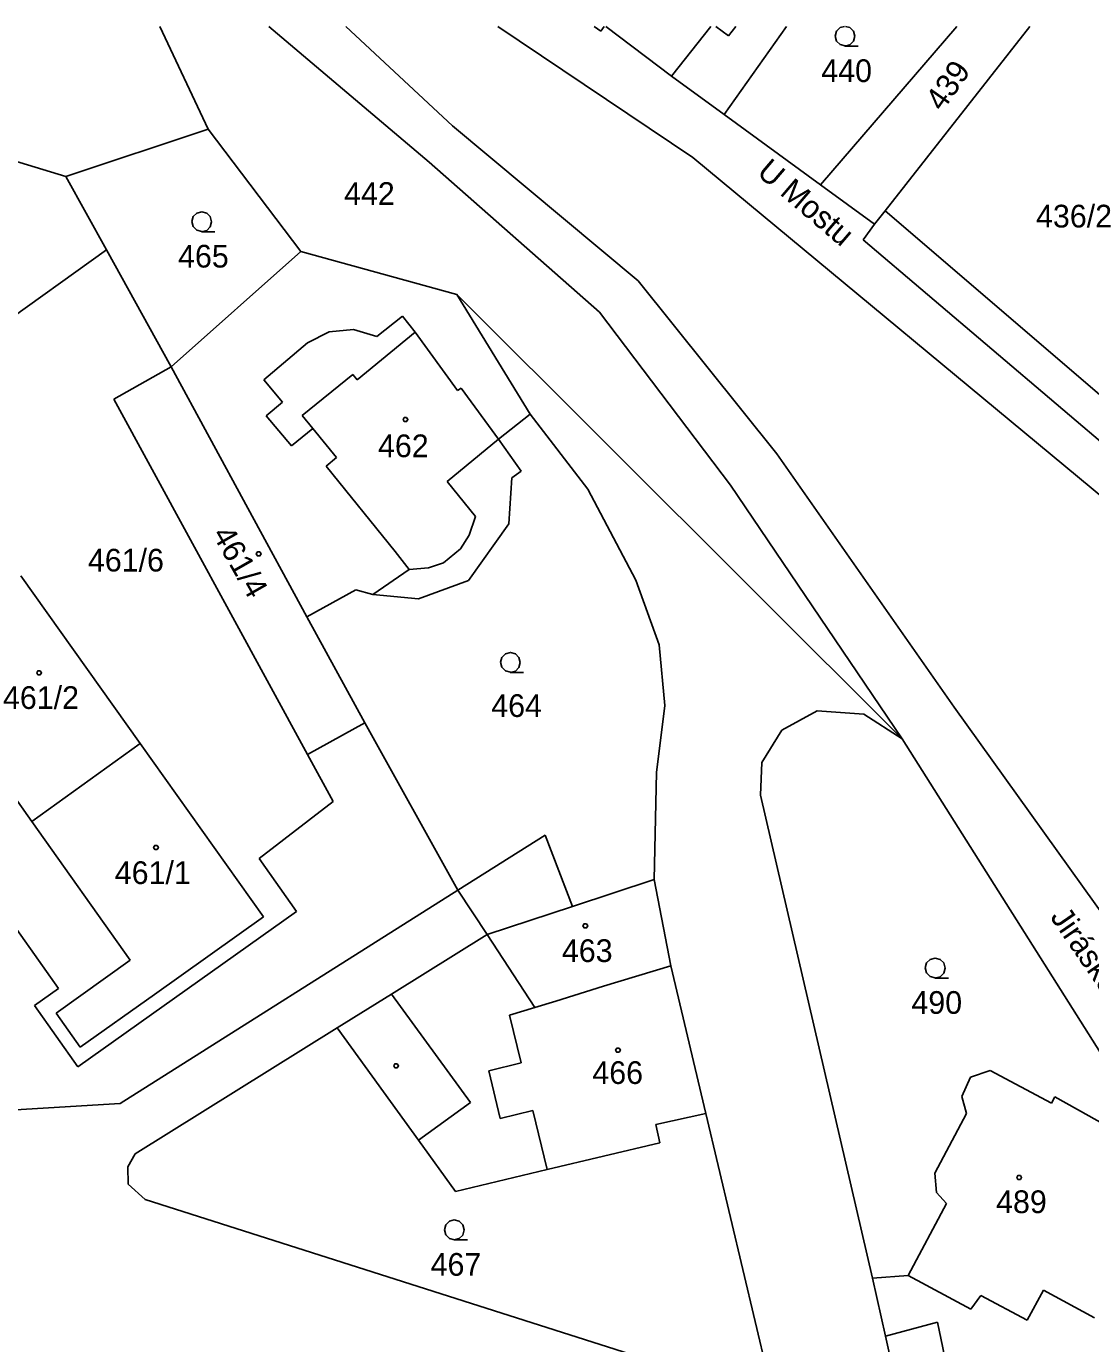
# Model space of a CAD drawing. Extents: x -621797 to -620972, y -1175539 to -1174697.
# Drawn here: x -621563.6 to -621483.9, y -1174797.6 to -1174699 of the extents above; entities that cross this region are included whole.
import ezdxf

# ---------------------------------------------------------------- set-up
doc = ezdxf.new("R2010")
doc.units = 0
for name, color, linetype in [('INZ mimo EON - nadz', 7, 'Continuous'), ('Rozvod plynu EON', 7, 'Continuous'), ('SDEL EON', 7, 'Continuous'), ('SDEL EON - popis', 7, 'Continuous'), ('Silnoproud EON', 7, 'Continuous'), ('Silnoproud EON - popis', 7, 'Continuous')]:
    doc.layers.add(name, color=color, linetype=linetype)

msp = doc.modelspace()

# ---------------------------------------------------------------- linework, layer by layer
at = {"layer": 'Rozvod plynu EON'}
for points in [[(-621535.1, -1174728.25), (-621535.01, -1174728.4), (-621535.1, -1174728.55), (-621535.28, -1174728.55), (-621535.37, -1174728.4), (-621535.28, -1174728.25)], [(-621546.09, -1174738.31), (-621546, -1174738.46), (-621546.09, -1174738.61), (-621546.27, -1174738.61), (-621546.36, -1174738.46), (-621546.27, -1174738.31)], [(-621562.53, -1174747.21), (-621562.44, -1174747.36), (-621562.53, -1174747.51), (-621562.71, -1174747.51), (-621562.8, -1174747.36), (-621562.71, -1174747.21)], [(-621553.78, -1174760.29), (-621553.69, -1174760.44), (-621553.78, -1174760.59), (-621553.96, -1174760.59), (-621554.05, -1174760.44), (-621553.96, -1174760.29)], [(-621521.63, -1174766.16), (-621521.54, -1174766.31), (-621521.63, -1174766.46), (-621521.81, -1174766.46), (-621521.9, -1174766.31), (-621521.81, -1174766.16)], [(-621519.19, -1174775.48), (-621519.1, -1174775.63), (-621519.19, -1174775.78), (-621519.37, -1174775.78), (-621519.46, -1174775.63), (-621519.37, -1174775.48)], [(-621535.8, -1174776.64), (-621535.71, -1174776.79), (-621535.8, -1174776.94), (-621535.98, -1174776.94), (-621536.07, -1174776.79), (-621535.98, -1174776.64)], [(-621489.15, -1174785), (-621489.06, -1174785.15), (-621489.15, -1174785.3), (-621489.33, -1174785.3), (-621489.42, -1174785.15), (-621489.33, -1174785)]]:
    msp.add_lwpolyline(points, close=True, dxfattribs=at)
at = {"layer": 'SDEL EON'}
for points in [[(-621502.27, -1174700.43), (-621502.65, -1174700.33), (-621502.92, -1174700.06), (-621503.02, -1174699.69), (-621502.92, -1174699.32), (-621502.65, -1174699.05), (-621502.317, -1174698.96)], [(-621502.243, -1174698.96), (-621501.91, -1174699.05), (-621501.64, -1174699.32), (-621501.54, -1174699.7), (-621501.64, -1174700.08), (-621501.91, -1174700.35), (-621502.29, -1174700.45), (-621501.29, -1174700.45)], [(-621550.43, -1174714.32), (-621550.81, -1174714.22), (-621551.08, -1174713.95), (-621551.18, -1174713.58), (-621551.08, -1174713.21), (-621550.81, -1174712.94), (-621550.44, -1174712.84), (-621550.07, -1174712.94), (-621549.8, -1174713.21), (-621549.7, -1174713.59), (-621549.8, -1174713.97), (-621550.07, -1174714.24), (-621550.45, -1174714.34), (-621549.45, -1174714.34)], [(-621527.32, -1174747.32), (-621527.7, -1174747.22), (-621527.97, -1174746.95), (-621528.07, -1174746.58), (-621527.97, -1174746.21), (-621527.7, -1174745.94), (-621527.33, -1174745.84), (-621526.96, -1174745.94), (-621526.69, -1174746.21), (-621526.59, -1174746.59), (-621526.69, -1174746.97), (-621526.96, -1174747.24), (-621527.34, -1174747.34), (-621526.34, -1174747.34)], [(-621495.52, -1174770.2), (-621495.9, -1174770.1), (-621496.17, -1174769.83), (-621496.27, -1174769.46), (-621496.17, -1174769.09), (-621495.9, -1174768.82), (-621495.53, -1174768.72), (-621495.16, -1174768.82), (-621494.89, -1174769.09), (-621494.79, -1174769.47), (-621494.89, -1174769.85), (-621495.16, -1174770.12), (-621495.54, -1174770.22), (-621494.54, -1174770.22)], [(-621531.52, -1174789.81), (-621531.9, -1174789.71), (-621532.17, -1174789.44), (-621532.27, -1174789.07), (-621532.17, -1174788.7), (-621531.9, -1174788.43), (-621531.53, -1174788.33), (-621531.16, -1174788.43), (-621530.89, -1174788.7), (-621530.79, -1174789.08), (-621530.89, -1174789.46), (-621531.16, -1174789.73), (-621531.54, -1174789.83), (-621530.54, -1174789.83)]]:
    msp.add_lwpolyline(points, dxfattribs=at)
at = {"layer": 'SDEL EON - popis'}
for p, q in [((-621545.428, -1174698.96), (-621533.41, -1174709.14)), ((-621512.314, -1174698.96), (-621515.26, -1174702.7)), ((-621511, -1174699.67), (-621511.952, -1174698.96)), ((-621510.45, -1174698.96), (-621511, -1174699.67)), ((-621533.41, -1174709.14), (-621520.65, -1174720.37)), ((-621499.28, -1174712.78), (-621465.93, -1174741.34)), ((-621498.01, -1174752.31), (-621531.35, -1174719.05)), ((-621535.41, -1174720.67), (-621537.33, -1174722.18)), ((-621534.45, -1174721.87), (-621535.41, -1174720.67)), ((-621520.65, -1174720.37), (-621510.84, -1174733.31)), ((-621540.89, -1174721.84), (-621542.52, -1174722.66)), ((-621539.08, -1174721.67), (-621540.89, -1174721.84)), ((-621537.33, -1174722.18), (-621539.08, -1174721.67)), ((-621538.8, -1174725.43), (-621534.45, -1174721.87)), ((-621534.45, -1174721.87), (-621531.28, -1174726.23)), ((-621542.52, -1174722.66), (-621545.8, -1174725.44)), ((-621542.92, -1174728.11), (-621539.14, -1174725.02)), ((-621539.14, -1174725.02), (-621538.8, -1174725.43)), ((-621545.8, -1174725.44), (-621544.39, -1174727.1)), ((-621531.28, -1174726.23), (-621531.01, -1174726.04)), ((-621531.01, -1174726.04), (-621528.22, -1174729.88)), ((-621544.39, -1174727.1), (-621545.63, -1174728.13)), ((-621545.63, -1174728.13), (-621543.71, -1174730.38)), ((-621542.13, -1174729.08), (-621542.92, -1174728.11)), ((-621543.71, -1174730.38), (-621542.13, -1174729.08)), ((-621540.35, -1174731.24), (-621542.13, -1174729.08)), ((-621528.22, -1174729.88), (-621532.07, -1174733.04)), ((-621541.12, -1174731.88), (-621540.35, -1174731.24)), ((-621535.96, -1174738.27), (-621541.12, -1174731.88)), ((-621532.07, -1174733.04), (-621529.95, -1174735.66)), ((-621510.84, -1174733.31), (-621498.01, -1174752.31)), ((-621529.95, -1174735.66), (-621530.42, -1174737.06)), ((-621530.42, -1174737.06), (-621531.06, -1174738.08)), ((-621534.91, -1174739.63), (-621535.96, -1174738.27)), ((-621531.06, -1174738.08), (-621532.35, -1174739.12)), ((-621534.91, -1174739.63), (-621537.64, -1174741.51)), ((-621533.46, -1174739.5), (-621534.91, -1174739.63)), ((-621532.35, -1174739.12), (-621533.46, -1174739.5)), ((-621522.67, -1174764.86), (-621529.06, -1174766.96)), ((-621536.24, -1174771.43), (-621530.31, -1174779.54)), ((-621525.51, -1174772.43), (-621527.39, -1174773)), ((-621527.39, -1174773), (-621526.52, -1174776.57)), ((-621526.52, -1174776.57), (-621528.95, -1174777.16)), ((-621528.95, -1174777.16), (-621528.09, -1174780.73)), ((-621530.31, -1174779.54), (-621534.21, -1174782.35)), ((-621528.09, -1174780.73), (-621525.65, -1174780.14)), ((-621525.65, -1174780.14), (-621524.58, -1174784.56)), ((-621492.86, -1174795.01), (-621497.54, -1174792.5)), ((-621492.11, -1174794), (-621492.86, -1174795.01)), ((-621488.64, -1174795.84), (-621492.11, -1174794)), ((-621487.41, -1174793.6), (-621488.64, -1174795.84)), ((-621483.6, -1174795.66), (-621487.41, -1174793.6)), ((-621499.24, -1174797.03), (-621495.36, -1174795.98)), ((-621495.36, -1174795.98), (-621494.43, -1174800.47))]:
    msp.add_line(p, q, dxfattribs=at)
at = {"layer": 'Silnoproud EON'}
for p, q in [((-621549.97, -1174706.67), (-621553.591, -1174698.96)), ((-621531.66, -1174706.42), (-621539.65, -1174698.96)), ((-621528.275, -1174698.96), (-621513.67, -1174708.79)), ((-621520.57, -1174699.33), (-621521.063, -1174698.96)), ((-621520.303, -1174698.96), (-621520.57, -1174699.33)), ((-621515.26, -1174702.7), (-621520.181, -1174698.96)), ((-621506.647, -1174698.96), (-621511.32, -1174705.57)), ((-621504.11, -1174710.83), (-621493.901, -1174698.96)), ((-621488.447, -1174698.96), (-621499.28, -1174712.78)), ((-621511.32, -1174705.57), (-621515.26, -1174702.7)), ((-621504.11, -1174710.83), (-621511.32, -1174705.57)), ((-621549.97, -1174706.67), (-621560.63, -1174710.21)), ((-621543.03, -1174715.81), (-621549.97, -1174706.67)), ((-621517.76, -1174718.01), (-621531.66, -1174706.42)), ((-621560.63, -1174710.21), (-621569.24, -1174707.58)), ((-621513.67, -1174708.79), (-621462.91, -1174750.9)), ((-621560.63, -1174710.21), (-621557.58, -1174715.7)), ((-621500.07, -1174713.78), (-621504.11, -1174710.83)), ((-621499.28, -1174712.78), (-621500.07, -1174713.78)), ((-621500.07, -1174713.78), (-621500.92, -1174714.95)), ((-621461.21, -1174748.72), (-621500.92, -1174714.95)), ((-621557.58, -1174715.7), (-621573.32, -1174726.98)), ((-621557.58, -1174715.7), (-621552.72, -1174724.46)), ((-621552.72, -1174724.46), (-621543.03, -1174715.81)), ((-621531.35, -1174719.05), (-621543.03, -1174715.81)), ((-621507.38, -1174730.98), (-621517.76, -1174718.01)), ((-621525.84, -1174728.01), (-621531.35, -1174719.05)), ((-621552.72, -1174724.46), (-621557.02, -1174726.87)), ((-621552.72, -1174724.46), (-621546.98, -1174735.04)), ((-621557.02, -1174726.87), (-621542.52, -1174753.47)), ((-621525.84, -1174728.01), (-621528.22, -1174729.88)), ((-621521.54, -1174733.61), (-621525.84, -1174728.01)), ((-621528.22, -1174729.88), (-621526.52, -1174732.26)), ((-621507.38, -1174730.98), (-621494.1, -1174749.94)), ((-621527.22, -1174732.76), (-621527.44, -1174736.21)), ((-621526.52, -1174732.26), (-621527.22, -1174732.76)), ((-621517.94, -1174740.44), (-621521.54, -1174733.61)), ((-621546.98, -1174735.04), (-621542.57, -1174743.17)), ((-621527.44, -1174736.21), (-621530.47, -1174740.46)), ((-621563.98, -1174740.11), (-621555.05, -1174752.66)), ((-621530.47, -1174740.46), (-621534.21, -1174741.83)), ((-621516.19, -1174745.28), (-621517.94, -1174740.44)), ((-621538.9, -1174741.16), (-621542.57, -1174743.17)), ((-621537.64, -1174741.51), (-621538.9, -1174741.16)), ((-621534.21, -1174741.83), (-621537.64, -1174741.51)), ((-621542.57, -1174743.17), (-621538.23, -1174751.1)), ((-621515.76, -1174749.81), (-621516.19, -1174745.28)), ((-621563.17, -1174758.49), (-621572.09, -1174745.92)), ((-621577.4, -1174748.06), (-621561.16, -1174771.01)), ((-621516.38, -1174754.84), (-621515.76, -1174749.81)), ((-621504.37, -1174750.21), (-621507.02, -1174751.66)), ((-621500.87, -1174750.45), (-621504.37, -1174750.21)), ((-621498.01, -1174752.31), (-621500.87, -1174750.45)), ((-621494.1, -1174749.94), (-621462.84, -1174793.62)), ((-621542.52, -1174753.47), (-621538.23, -1174751.1)), ((-621538.23, -1174751.1), (-621531.27, -1174763.65)), ((-621507.02, -1174751.66), (-621508.5, -1174754.08)), ((-621555.05, -1174752.66), (-621563.17, -1174758.49)), ((-621555.05, -1174752.66), (-621545.81, -1174765.64)), ((-621476.96, -1174785.62), (-621498.01, -1174752.31)), ((-621540.6, -1174756.99), (-621542.52, -1174753.47)), ((-621508.5, -1174754.08), (-621508.6, -1174756.53)), ((-621516.57, -1174762.85), (-621516.38, -1174754.84)), ((-621508.6, -1174756.53), (-621500.21, -1174792.69)), ((-621546.15, -1174761.28), (-621540.6, -1174756.99)), ((-621555.81, -1174768.87), (-621563.17, -1174758.49)), ((-621531.27, -1174763.65), (-621524.74, -1174759.53)), ((-621524.74, -1174759.53), (-621522.67, -1174764.86)), ((-621543.34, -1174765.23), (-621546.15, -1174761.28)), ((-621516.57, -1174762.85), (-621522.67, -1174764.86)), ((-621515.33, -1174769.3), (-621516.57, -1174762.85)), ((-621531.27, -1174763.65), (-621556.56, -1174779.61)), ((-621531.27, -1174763.65), (-621529.06, -1174766.96)), ((-621559.73, -1174776.87), (-621543.34, -1174765.23)), ((-621545.81, -1174765.64), (-621553.98, -1174771.44)), ((-621529.06, -1174766.96), (-621536.24, -1174771.43)), ((-621525.51, -1174772.43), (-621529.06, -1174766.96)), ((-621561.34, -1174772.85), (-621555.81, -1174768.87)), ((-621515.33, -1174769.3), (-621520.35, -1174770.84)), ((-621512.71, -1174780.35), (-621515.33, -1174769.3)), ((-621561.16, -1174771.01), (-621562.97, -1174772.28)), ((-621553.98, -1174771.44), (-621559.55, -1174775.4)), ((-621536.24, -1174771.43), (-621540.29, -1174773.95)), ((-621520.35, -1174770.84), (-621523.92, -1174771.94)), ((-621562.97, -1174772.28), (-621559.73, -1174776.87)), ((-621523.92, -1174771.94), (-621525.51, -1174772.43)), ((-621559.55, -1174775.4), (-621561.34, -1174772.85)), ((-621540.29, -1174773.95), (-621555.42, -1174783.39)), ((-621534.21, -1174782.35), (-621540.29, -1174773.95)), ((-621492.89, -1174777.64), (-621491.42, -1174777.14)), ((-621491.42, -1174777.14), (-621486.81, -1174779.59)), ((-621493.54, -1174779.1), (-621492.89, -1174777.64)), ((-621493.17, -1174780.35), (-621493.54, -1174779.1)), ((-621486.81, -1174779.59), (-621486.57, -1174779.12)), ((-621486.57, -1174779.12), (-621481.69, -1174781.84)), ((-621556.56, -1174779.61), (-621565.21, -1174780.14)), ((-621512.71, -1174780.35), (-621516.45, -1174781.18)), ((-621516.45, -1174781.18), (-621516.14, -1174782.56)), ((-621508.02, -1174800.1), (-621512.71, -1174780.35)), ((-621495.56, -1174784.83), (-621493.17, -1174780.35)), ((-621531.43, -1174786.19), (-621534.21, -1174782.35)), ((-621516.14, -1174782.56), (-621524.58, -1174784.56)), ((-621555.42, -1174783.39), (-621555.97, -1174784.35)), ((-621555.96, -1174785.65), (-621555.97, -1174784.35)), ((-621524.58, -1174784.56), (-621531.43, -1174786.19)), ((-621495.56, -1174784.83), (-621495.43, -1174786.28)), ((-621554.68, -1174786.81), (-621555.96, -1174785.65)), ((-621509.05, -1174801.33), (-621554.68, -1174786.81)), ((-621497.54, -1174792.5), (-621494.68, -1174787.1)), ((-621495.43, -1174786.28), (-621494.68, -1174787.1)), ((-621500.21, -1174792.69), (-621497.54, -1174792.5)), ((-621500.21, -1174792.69), (-621499.24, -1174797.03)), ((-621499.24, -1174797.03), (-621497.47, -1174804.88))]:
    msp.add_line(p, q, dxfattribs=at)

# ---------------------------------------------------------------- texts
at = {"layer": 'INZ mimo EON - nadz'}
for s, rotation, p in [('U Mostu', 319.48127, (-621508.959, -1174710.032)), ('Jiráskova', 304.52707, (-621486.963, -1174765.659))]:
    msp.add_text(s, height=1.7, rotation=rotation, dxfattribs=at).set_placement(p)
at = {"layer": 'Silnoproud EON - popis'}
for s, p in [('440', (-621504.053, -1174703.13)), ('442', (-621539.783, -1174712.33)), ('436/2', (-621487.973, -1174714.02)), ('465', (-621552.213, -1174717.02)), ('462', (-621537.243, -1174731.22)), ('461/6', (-621558.963, -1174739.78)), ('461/2', (-621565.323, -1174750.07)), ('464', (-621528.763, -1174750.67)), ('461/1', (-621556.953, -1174763.18)), ('463', (-621523.473, -1174769.02)), ('490', (-621497.303, -1174772.9)), ('466', (-621521.193, -1174778.15)), ('489', (-621490.963, -1174787.82)), ('467', (-621533.303, -1174792.51))]:
    msp.add_text(s, height=1.7, dxfattribs=at).set_placement(p)
for s, rotation, p in [('439', 54.88936, (-621494.993, -1174705.406)), ('461/4', 299.71422, (-621549.702, -1174736.986))]:
    msp.add_text(s, height=1.7, rotation=rotation, dxfattribs=at).set_placement(p)

doc.saveas('drawing.dxf')
